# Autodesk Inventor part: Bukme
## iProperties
Created: 2009-12
Part Number: Bukme
Document SubType Name: Modeling
Designer: bulent
Density: 1 g/cm^3
Author: bulent
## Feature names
1. Extrusion1
2. Extrusion2
